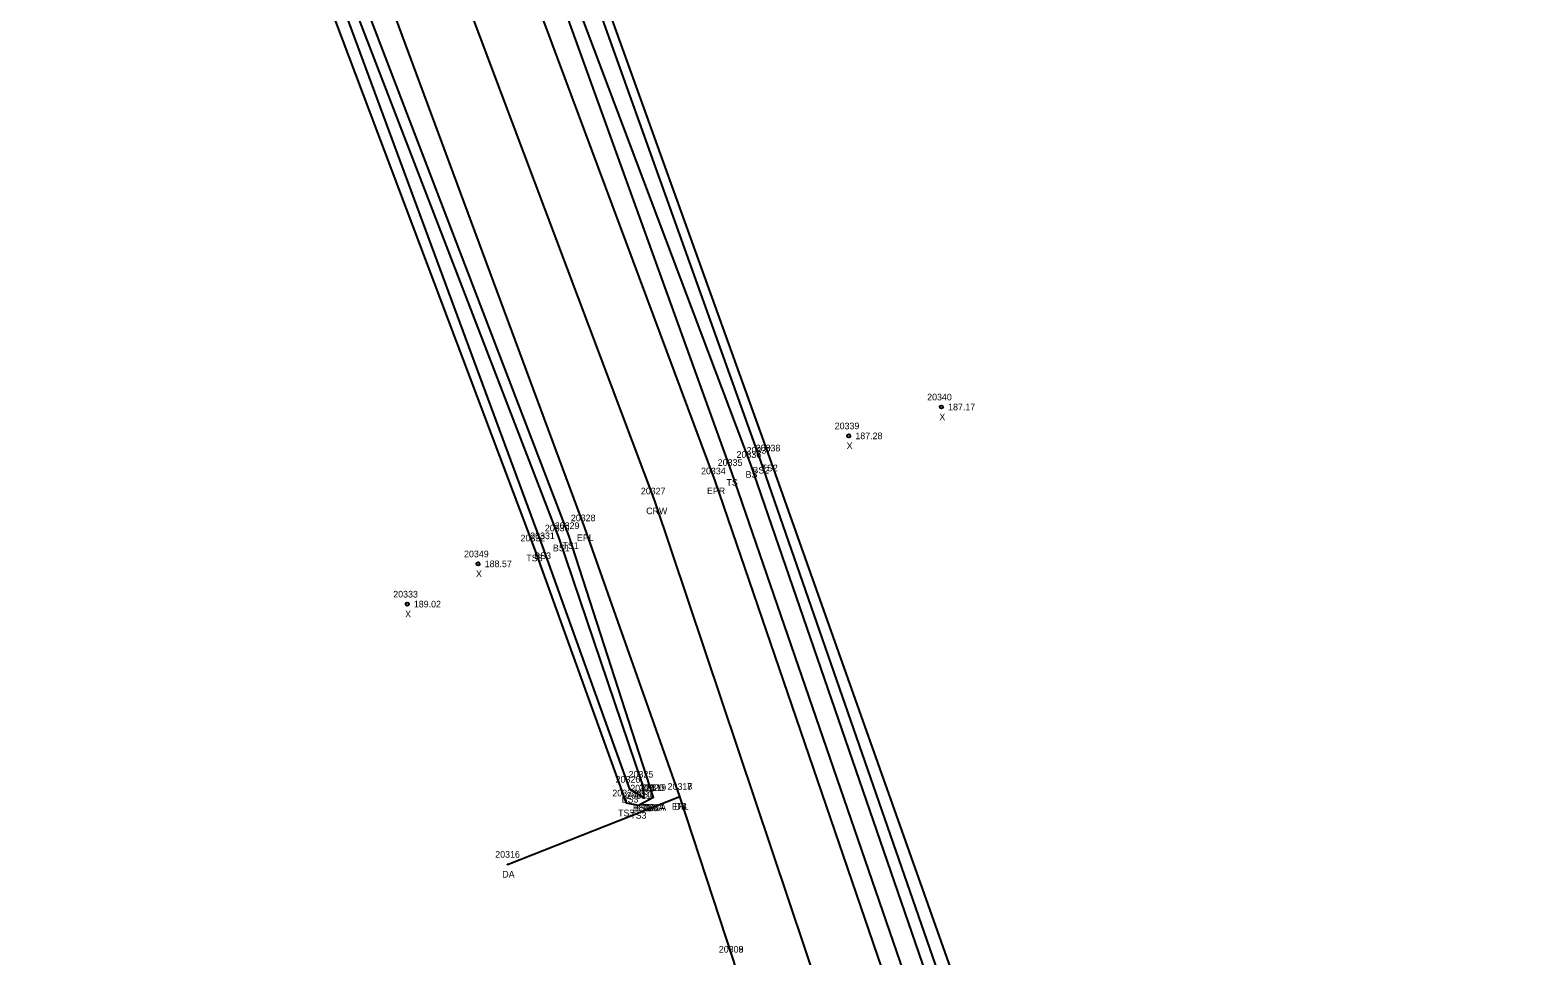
# Model space of a CAD drawing. Extents: x 2077883 to 2078272, y 787819 to 788945.
# Drawn here: x 2077906.8 to 2078134.4, y 788665.6 to 788805.4 of the extents above; entities that cross this region are included whole.
import ezdxf

# ---------------------------------------------------------------- set-up
doc = ezdxf.new("R2010")
doc.units = 0
for name, color, linetype in [('RD_DTM_BkLn1', 7, 'Continuous'), ('RD_DTM_BkLn2', 7, 'Continuous'), ('RD_EX_Driveway', 7, 'Continuous'), ('RD_EX_Driveway_txCode', 7, 'Continuous'), ('RD_EX_Road', 7, 'Continuous'), ('RD_EX_Road_txCode', 7, 'Continuous'), ('RD_Sketch8', 7, 'Continuous'), ('RD_SMD_Locator', 7, 'Continuous'), ('RD_SMD_Misc', 7, 'Continuous')]:
    doc.layers.add(name, color=color, linetype=linetype)

msp = doc.modelspace()

# ---------------------------------------------------------------- linework, layer by layer
at = {"layer": 'RD_DTM_BkLn1'}
msp.add_lwpolyline([(2078089.54, 788425.19), (2078086.71, 788437.21), (2078062.2, 788536.79), (2078033.97, 788636.37), (2078001.1, 788734.32), (2077964.77, 788830.93), (2077924.88, 788926.7)], dxfattribs=at)
at = {"layer": 'RD_DTM_BkLn2'}
for points in [[(2078130.39, 788474.32), (2078119.21, 788468.58), (2078104.21, 788490.29), (2078085.93, 788526.63), (2078081.69, 788541.53), (2078065.4, 788601.95), (2078053.34, 788642.42), (2078018.45, 788740.81), (2077983.36, 788838.44), (2077944.78, 788934.86)], [(2078133.54, 788471.13), (2078119.08, 788459.82), (2078109.91, 788458.97), (2078096.37, 788486), (2078083.98, 788526.2), (2078079.55, 788541.15), (2078062.23, 788600.27), (2078049.45, 788641.41), (2078015.58, 788739.83), (2077979.12, 788836.63), (2077939.6, 788933.24)], [(2078132.44, 788472.19), (2078118.34, 788466.81), (2078100.1, 788488.15), (2078085.17, 788526.48), (2078080.48, 788541.38), (2078063.7, 788600.7), (2078051.16, 788642.09), (2078017.07, 788740.46), (2077982.21, 788837.85), (2077942.69, 788934.33)], [(2078134.43, 788470.29), (2078120, 788457.99), (2078107.89, 788457.91), (2078093.72, 788484.84), (2078082.52, 788526.41), (2078077.77, 788540.75), (2078060.01, 788599.41), (2078046.63, 788640.05), (2078012.72, 788738.62), (2077977.66, 788835.93), (2077936.62, 788932.18)], [(2078000.92, 788689.53), (2077988.11, 788729.08), (2077951.02, 788825.94), (2077912.79, 788921.47)], [(2078000.92, 788689.53), (2077998.64, 788688.34), (2077996.8, 788688.7), (2077982.94, 788727.21), (2077946.28, 788824.41), (2077906.77, 788919.04)], [(2077999.51, 788689.45), (2077997.32, 788690.77), (2077984.12, 788727.55), (2077948.07, 788825.25), (2077908.52, 788919.97)], [(2077999.51, 788689.45), (2077999.26, 788691.54), (2077986.65, 788728.72), (2077949.41, 788825.41), (2077910.63, 788920.58)]]:
    msp.add_lwpolyline(points, dxfattribs=at)
at = {"layer": 'RD_EX_Driveway'}
msp.add_line((2077978.86, 788679.44), (2078004.86, 788689.7), dxfattribs=at)
at = {"layer": 'RD_EX_Road'}
for points in [[(2078107.13, 788420.86), (2078105.11, 788427.29), (2078111.84, 788429.2), (2078117.69, 788434.7), (2078115.66, 788443.13), (2078106.49, 788447.64), (2078097.77, 788449.71), (2078094.97, 788456.34), (2078072.64, 788539.43), (2078043.77, 788639.22), (2078010.2, 788737.35), (2077974.01, 788834.54), (2077934.07, 788930.86)], [(2078107.13, 788420.86), (2078092.81, 788417.62), (2078089.54, 788425.19), (2078083.84, 788425.84), (2078081.3, 788430.73), (2078074.53, 788432.67), (2078073.43, 788440.66), (2078071.07, 788452.5), (2078051.67, 788533.56), (2078023.01, 788633.14), (2078012.91, 788665.11), (2078004.86, 788689.7), (2077990.53, 788730.26), (2077954.65, 788827.14), (2077915.26, 788922.36)]]:
    msp.add_lwpolyline(points, dxfattribs=at)
at = {"layer": 'RD_SMD_Locator'}
for centre, radius in [((2078044.38, 788748.51), 0.25), ((2078030.38, 788744.15), 0.25), ((2078015.58, 788739.83), 0.001), ((2078017.07, 788740.46), 0.001), ((2078018.45, 788740.81), 0.001), ((2078010.2, 788737.35), 0.001), ((2078012.72, 788738.62), 0.001), ((2078001.1, 788734.32), 0.001), ((2077990.53, 788730.26), 0.001), ((2077986.65, 788728.72), 0.001), ((2077988.11, 788729.08), 0.001), ((2077982.94, 788727.21), 0.001), ((2077984.12, 788727.55), 0.001), ((2077974.41, 788724.82), 0.25), ((2077963.71, 788718.74), 0.25), ((2077999.26, 788691.54), 0.001), ((2077997.32, 788690.77), 0.001), ((2077999.51, 788689.45), 0.001), ((2077999.51, 788689.45), 0.001), ((2078000.92, 788689.53), 0.001), ((2078000.92, 788689.53), 0.001), ((2078004.86, 788689.7), 0.001), ((2078004.86, 788689.7), 0.001), ((2077996.8, 788688.7), 0.001), ((2077998.64, 788688.34), 0.001), ((2077978.86, 788679.44), 0.001)]:
    msp.add_circle(centre, radius, dxfattribs=at)

# ---------------------------------------------------------------- texts
at = {"layer": 'RD_EX_Driveway_txCode'}
for s, p in [('20317', (2078003.03, 788690.7)), ('DB', (2078004.08, 788687.7)), ('20316', (2077977, 788680.44)), ('DA', (2077978.06, 788677.44)), ('20309', (2078010.76, 788666.11))]:
    msp.add_text(s, height=1, dxfattribs=at).set_placement(p)
at = {"layer": 'RD_EX_Road_txCode'}
for s, p in [('20334', (2078008.08, 788738.35)), ('EPR', (2078008.97, 788735.35)), ('20328', (2077988.42, 788731.26)), ('EPL', (2077989.33, 788728.26)), ('20318', (2078003.03, 788690.7)), ('EPL', (2078003.66, 788687.7)), ('20308', (2078010.76, 788666.11))]:
    msp.add_text(s, height=1, dxfattribs=at).set_placement(p)
at = {"layer": 'RD_Sketch8'}
for s, p in [('20340', (2078042.22, 788749.51)), ('187.17', (2078045.38, 788748.01)), ('20339', (2078028.26, 788745.15)), ('X', (2078044.06, 788746.51)), ('187.28', (2078031.38, 788743.65)), ('X', (2078030.06, 788742.15)), ('20349', (2077972.29, 788725.82)), ('188.57', (2077975.41, 788724.32)), ('X', (2077974.09, 788722.82)), ('20333', (2077961.6, 788719.74)), ('189.02', (2077964.71, 788718.24)), ('X', (2077963.4, 788716.74))]:
    msp.add_text(s, height=1, dxfattribs=at).set_placement(p)
at = {"layer": 'RD_SMD_Misc'}
for s, p in [('20336', (2078013.44, 788740.83)), ('20337', (2078014.95, 788741.46)), ('20338', (2078016.33, 788741.81)), ('20335', (2078010.6, 788739.62)), ('BS2', (2078015.84, 788738.46)), ('TS2', (2078017.21, 788738.81)), ('TS', (2078011.92, 788736.62)), ('BS', (2078014.8, 788737.83)), ('20327', (2077998.99, 788735.32)), ('CRW', (2077999.79, 788732.32)), ('20330', (2077984.49, 788729.72)), ('20329', (2077985.99, 788730.08)), ('20332', (2077980.82, 788728.21)), ('20331', (2077982.28, 788728.55)), ('BS1', (2077985.71, 788726.72)), ('TS1', (2077987.15, 788727.08)), ('TS3', (2077981.69, 788725.21)), ('BS3', (2077982.89, 788725.55)), ('20325', (2077997.14, 788692.54)), ('20326', (2077995.18, 788691.77)), ('20323', (2077997.39, 788690.45)), ('20324', (2077997.39, 788690.45)), ('20320', (2077998.76, 788690.53)), ('20319', (2077999.08, 788690.53)), ('20322', (2077994.68, 788689.7)), ('BS3', (2077996.09, 788688.77)), ('20321', (2077996.8, 788689.34)), ('BS1', (2077998.31, 788689.54)), ('TS3', (2077995.55, 788686.7)), ('TS3', (2077997.39, 788686.34)), ('BS3A', (2077997.79, 788687.45)), ('BS1A', (2077998.07, 788687.45)), ('TS3A', (2077999.18, 788687.53)), ('TS1A', (2077999.47, 788687.53))]:
    msp.add_text(s, height=1, dxfattribs=at).set_placement(p)

doc.saveas('drawing.dxf')
